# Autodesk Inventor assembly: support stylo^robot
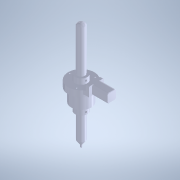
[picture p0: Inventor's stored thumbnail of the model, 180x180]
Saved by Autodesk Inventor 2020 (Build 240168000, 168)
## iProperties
Created: 2018-10
Part Number: support stylo^robot
Document SubType Name: Assembly
Designer: bruno
Mass: 27.712 g
Surface Area: 166.101 cm^2
Volume: 27.712 cm^3
Density: 1 g/cm^3
Sending System: SolidWorks 2016
Last Author: Prof
Last Saved: 2018-10-03
Author: bruno
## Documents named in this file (5)
- C:\Users\bruno\Documents\Systèmes\Mallette Bras robotisé (273265)\Dossier ressources\Maquette Dobot SW2016\support stylo^robot.iam
- C:\Users\bruno\Documents\Systèmes\Mallette Bras robotisé (273265)\Dossier ressources\Maquette Dobot SW2016\___2_A.ipt
- C:\Users\bruno\Documents\Systèmes\Mallette Bras robotisé (273265)\Dossier ressources\Maquette Dobot SW2016\_____2_A.ipt
- C:\Users\bruno\Documents\Systèmes\Mallette Bras robotisé (273265)\Dossier ressources\Maquette Dobot SW2016\____2_A.ipt
- C:\Users\bruno\Documents\Systèmes\Mallette Bras robotisé (273265)\Dossier ressources\Maquette Dobot SW2016\___-_2_A.ipt
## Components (4 placed, 4 different names)
1. ___2_A:1
2. _____2_A:1
3. ____2_A:1 — Placage:1
4. ___-_2_A:1 — Placage:1
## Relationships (1: Mate 1)
- Placage:1 [Mate]: ____2_A:1 ↔ ___-_2_A:1
